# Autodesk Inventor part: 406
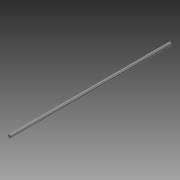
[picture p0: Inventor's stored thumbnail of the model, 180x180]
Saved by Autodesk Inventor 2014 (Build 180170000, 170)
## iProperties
Created: 2013-12
Part Number: 406
Material: Stainless Steel
Document SubType Name: Modeling
Designer: Bram
Density: 8.08 g/cm^3
Appearance: Semi-Polished
Author: Bram
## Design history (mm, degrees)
sketch "Sketch1"
  geometry: C1 r 4 at (0, 0); 1 further point
  constraints: 1 centre point, 1 coincident
  dimensions: "d0" = 8 diameter of C1
extrude "Extrusion1" new body sketch "Sketch1" distance "d1" = 406; taper "d2" = 0 deg
body "Solid1"
